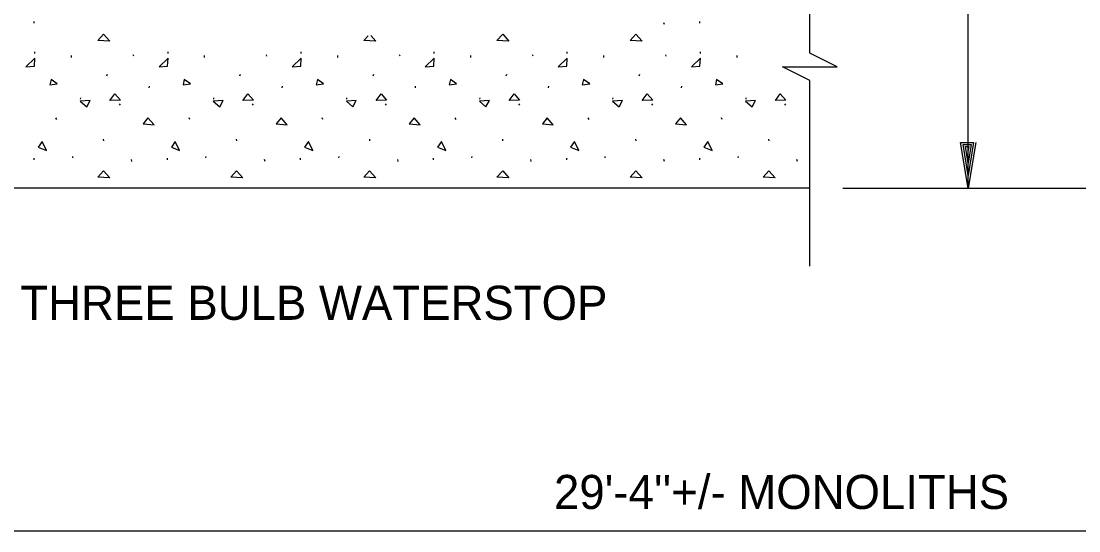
# Model space of a CAD drawing. Extents: x 22369.6 to 22384.3, y 22369.6 to 22381.8.
# Drawn here: x 22372.573 to 22374.021, y 22378.143 to 22378.84 of the extents above; entities that cross this region are included whole.
import ezdxf

# ---------------------------------------------------------------- set-up
doc = ezdxf.new("R2010")
doc.units = 0
for name, color, linetype in [('Level 1', 7, 'Continuous'), ('Level 10', 7, 'Continuous'), ('Level 4', 7, 'Continuous'), ('Level 8', 7, 'Continuous')]:
    doc.layers.add(name, color=color, linetype=linetype)

msp = doc.modelspace()

# ---------------------------------------------------------------- linework, layer by layer
at = {"layer": 'Level 1'}
for p, q in [((22373.6529, 22378.7964), (22373.6529, 22379.4351)), ((22373.8696, 22378.6119), (22373.8696, 22379.1117)), ((22373.6529, 22378.5051), (22373.6529, 22378.759)), ((22373.8696, 22378.6292), (22373.8696, 22378.6292)), ((22373.698, 22378.6119), (22374.3215, 22378.6119)), ((22373.8696, 22378.6119), (22373.8696, 22378.6119)), ((22372.3014, 22378.1431), (22374.1817, 22378.1431))]:
    msp.add_line(p, q, dxfattribs=at)
for points in [[(22373.6529, 22378.759), (22373.6154, 22378.7777), (22373.6904, 22378.7777), (22373.6529, 22378.7964)], [(22373.8799, 22378.6742), (22373.8696, 22378.6119), (22373.8592, 22378.6742), (22373.8769, 22378.6742), (22373.8696, 22378.6292), (22373.8626, 22378.6716), (22373.8739, 22378.6716), (22373.8696, 22378.6459), (22373.8659, 22378.6689), (22373.8706, 22378.6689), (22373.8696, 22378.6632)]]:
    msp.add_lwpolyline(points, dxfattribs=at)
at = {"layer": 'Level 10'}
msp.add_line((22373.6529, 22378.6119), (22372.3535, 22378.6119), dxfattribs=at)
at = {"layer": 'Level 8'}
for p, q in [((22372.5911, 22378.8374), (22372.5911, 22378.8399)), ((22373.4537, 22378.8354), (22373.453, 22378.8379)), ((22373.5022, 22378.8374), (22373.5022, 22378.8399)), ((22372.592, 22378.796), (22372.592, 22378.7983)), ((22372.6421, 22378.7906), (22372.6421, 22378.7931)), ((22372.7273, 22378.7923), (22372.7266, 22378.7941)), ((22372.7742, 22378.796), (22372.7742, 22378.7983)), ((22372.8243, 22378.7906), (22372.8243, 22378.7931)), ((22372.9096, 22378.7923), (22372.9088, 22378.7941)), ((22372.9564, 22378.796), (22372.9564, 22378.7983)), ((22373.0066, 22378.7906), (22373.0066, 22378.7931)), ((22373.0918, 22378.7923), (22373.0911, 22378.7941)), ((22373.1386, 22378.796), (22373.1386, 22378.7983)), ((22373.1888, 22378.7906), (22373.1888, 22378.7931)), ((22373.274, 22378.7923), (22373.2733, 22378.7941)), ((22373.3208, 22378.796), (22373.3208, 22378.7983)), ((22373.371, 22378.7906), (22373.371, 22378.7931)), ((22373.4562, 22378.7923), (22373.4555, 22378.7941)), ((22373.5031, 22378.796), (22373.5031, 22378.7983)), ((22373.5532, 22378.7906), (22373.5532, 22378.7931)), ((22372.6905, 22378.7656), (22372.6914, 22378.7676)), ((22372.8727, 22378.7656), (22372.8736, 22378.7676)), ((22373.0549, 22378.7656), (22373.0558, 22378.7676)), ((22373.2371, 22378.7656), (22373.2381, 22378.7676)), ((22373.4193, 22378.7656), (22373.4203, 22378.7676)), ((22372.7483, 22378.7488), (22372.7487, 22378.7512)), ((22372.9306, 22378.7488), (22372.9309, 22378.7512)), ((22373.1128, 22378.7488), (22373.1131, 22378.7512)), ((22373.295, 22378.7488), (22373.2953, 22378.7512)), ((22373.4772, 22378.7488), (22373.4776, 22378.7512)), ((22372.6545, 22378.7336), (22372.6547, 22378.7354)), ((22372.8367, 22378.7336), (22372.8369, 22378.7354)), ((22373.0189, 22378.7336), (22373.0191, 22378.7354)), ((22373.2011, 22378.7336), (22373.2013, 22378.7354)), ((22373.3833, 22378.7336), (22373.3835, 22378.7354)), ((22373.5656, 22378.7336), (22373.5657, 22378.7354)), ((22372.7077, 22378.7253), (22372.709, 22378.7273)), ((22372.8899, 22378.7253), (22372.8912, 22378.7273)), ((22373.0721, 22378.7253), (22373.0734, 22378.7273)), ((22373.2543, 22378.7253), (22373.2556, 22378.7273)), ((22373.4366, 22378.7253), (22373.4378, 22378.7273)), ((22373.6188, 22378.7253), (22373.62, 22378.7273)), ((22372.6219, 22378.7058), (22372.6208, 22378.708)), ((22372.8041, 22378.7058), (22372.803, 22378.708)), ((22372.9863, 22378.7058), (22372.9852, 22378.708)), ((22373.1685, 22378.7058), (22373.1674, 22378.708)), ((22373.3507, 22378.7058), (22373.3496, 22378.708)), ((22373.5329, 22378.7058), (22373.5318, 22378.708)), ((22372.6861, 22378.6767), (22372.6859, 22378.6788)), ((22372.8683, 22378.6767), (22372.8681, 22378.6788)), ((22373.0505, 22378.6767), (22373.0503, 22378.6788)), ((22373.2327, 22378.6767), (22373.2325, 22378.6788)), ((22373.4149, 22378.6767), (22373.4147, 22378.6788)), ((22373.5971, 22378.6767), (22373.5969, 22378.6788)), ((22372.5911, 22378.6504), (22372.5911, 22378.6529)), ((22372.6437, 22378.6533), (22372.644, 22378.6552)), ((22372.7248, 22378.6484), (22372.7241, 22378.6509)), ((22372.7733, 22378.6504), (22372.7733, 22378.6529)), ((22372.8259, 22378.6533), (22372.8262, 22378.6552)), ((22372.9071, 22378.6484), (22372.9063, 22378.6509)), ((22372.9556, 22378.6504), (22372.9556, 22378.6529)), ((22373.0081, 22378.6533), (22373.0084, 22378.6552)), ((22373.0893, 22378.6484), (22373.0886, 22378.6509)), ((22373.1378, 22378.6504), (22373.1378, 22378.6529)), ((22373.1903, 22378.6533), (22373.1906, 22378.6552)), ((22373.2715, 22378.6484), (22373.2708, 22378.6509)), ((22373.32, 22378.6504), (22373.32, 22378.6529)), ((22373.3725, 22378.6533), (22373.3728, 22378.6552)), ((22373.4537, 22378.6484), (22373.453, 22378.6509)), ((22373.5022, 22378.6504), (22373.5022, 22378.6529)), ((22373.5547, 22378.6533), (22373.5551, 22378.6552)), ((22373.6359, 22378.6484), (22373.6352, 22378.6509))]:
    msp.add_line(p, q, dxfattribs=at)
for points in [[(22372.6779, 22378.8137), (22372.6858, 22378.8223)], [(22372.6858, 22378.8223), (22372.6943, 22378.8128)], [(22373.0423, 22378.8137), (22373.0483, 22378.8202)], [(22373.0519, 22378.8204), (22373.0587, 22378.8128)], [(22372.6943, 22378.8128), (22372.6779, 22378.8137)], [(22373.0587, 22378.8128), (22373.0423, 22378.8137)]]:
    msp.add_lwpolyline(points, dxfattribs=at)
for points in [[(22373.2245, 22378.8137), (22373.2324, 22378.8223), (22373.2409, 22378.8128)], [(22373.4067, 22378.8137), (22373.4146, 22378.8223), (22373.4231, 22378.8128)], [(22372.5914, 22378.7786), (22372.592, 22378.7897), (22372.5797, 22378.7777)], [(22372.7736, 22378.7786), (22372.7742, 22378.7897), (22372.7619, 22378.7777)], [(22372.9558, 22378.7786), (22372.9564, 22378.7897), (22372.9441, 22378.7777)], [(22373.138, 22378.7786), (22373.1386, 22378.7897), (22373.1263, 22378.7777)], [(22373.3202, 22378.7786), (22373.3208, 22378.7897), (22373.3085, 22378.7777)], [(22373.5024, 22378.7786), (22373.5031, 22378.7897), (22373.4907, 22378.7777)], [(22372.6125, 22378.7532), (22372.6226, 22378.7545), (22372.6141, 22378.7602)], [(22372.7947, 22378.7532), (22372.8048, 22378.7545), (22372.7963, 22378.7602)], [(22372.9769, 22378.7532), (22372.9871, 22378.7545), (22372.9786, 22378.7602)], [(22373.1591, 22378.7532), (22373.1693, 22378.7545), (22373.1608, 22378.7602)], [(22373.3413, 22378.7532), (22373.3515, 22378.7545), (22373.343, 22378.7602)], [(22373.5236, 22378.7532), (22373.5337, 22378.7545), (22373.5252, 22378.7602)], [(22372.6539, 22378.7309), (22372.6628, 22378.723), (22372.6675, 22378.7318)], [(22372.6946, 22378.7318), (22372.7013, 22378.7407), (22372.7089, 22378.7322)], [(22372.8361, 22378.7309), (22372.845, 22378.723), (22372.8497, 22378.7318)], [(22372.8768, 22378.7318), (22372.8836, 22378.7407), (22372.8911, 22378.7322)], [(22373.0183, 22378.7309), (22373.0272, 22378.723), (22373.0319, 22378.7318)], [(22373.0591, 22378.7318), (22373.0658, 22378.7407), (22373.0733, 22378.7322)], [(22373.2005, 22378.7309), (22373.2094, 22378.723), (22373.2141, 22378.7318)], [(22373.2413, 22378.7318), (22373.248, 22378.7407), (22373.2555, 22378.7322)], [(22373.3827, 22378.7309), (22373.3916, 22378.723), (22373.3963, 22378.7318)], [(22373.4235, 22378.7318), (22373.4302, 22378.7407), (22373.4377, 22378.7322)], [(22373.5649, 22378.7309), (22373.5738, 22378.723), (22373.5786, 22378.7318)], [(22373.6057, 22378.7318), (22373.6124, 22378.7407), (22373.6199, 22378.7322)], [(22372.755, 22378.6983), (22372.7467, 22378.7078), (22372.7401, 22378.6999)], [(22372.9372, 22378.6983), (22372.9289, 22378.7078), (22372.9223, 22378.6999)], [(22373.1194, 22378.6983), (22373.1111, 22378.7078), (22373.1045, 22378.6999)], [(22373.3016, 22378.6983), (22373.2933, 22378.7078), (22373.2867, 22378.6999)], [(22373.4838, 22378.6983), (22373.4756, 22378.7078), (22373.4689, 22378.6999)], [(22372.5966, 22378.6679), (22372.6079, 22378.6635), (22372.6019, 22378.6758)], [(22372.7788, 22378.6679), (22372.7901, 22378.6635), (22372.7841, 22378.6758)], [(22372.961, 22378.6679), (22372.9723, 22378.6635), (22372.9663, 22378.6758)], [(22373.1432, 22378.6679), (22373.1546, 22378.6635), (22373.1486, 22378.6758)], [(22373.3254, 22378.6679), (22373.3368, 22378.6635), (22373.3308, 22378.6758)], [(22373.5076, 22378.6679), (22373.519, 22378.6635), (22373.513, 22378.6758)], [(22372.6779, 22378.6267), (22372.6858, 22378.6353), (22372.6943, 22378.6258)], [(22372.8601, 22378.6267), (22372.868, 22378.6353), (22372.8765, 22378.6258)], [(22373.0423, 22378.6267), (22373.0502, 22378.6353), (22373.0587, 22378.6258)], [(22373.2245, 22378.6267), (22373.2324, 22378.6353), (22373.2409, 22378.6258)], [(22373.4067, 22378.6267), (22373.4146, 22378.6353), (22373.4231, 22378.6258)], [(22373.5889, 22378.6267), (22373.5968, 22378.6353), (22373.6053, 22378.6258)]]:
    msp.add_lwpolyline(points, close=True, dxfattribs=at)

# ---------------------------------------------------------------- texts
at = {"layer": 'Level 4'}
for s, p in [('THREE BULB WATERSTOP', (22372.572, 22378.4317)), ("29'-4''+/- MONOLITHS", (22373.3026, 22378.173))]:
    msp.add_text(s, height=0.046625, dxfattribs=at).set_placement(p)

doc.saveas('drawing.dxf')
